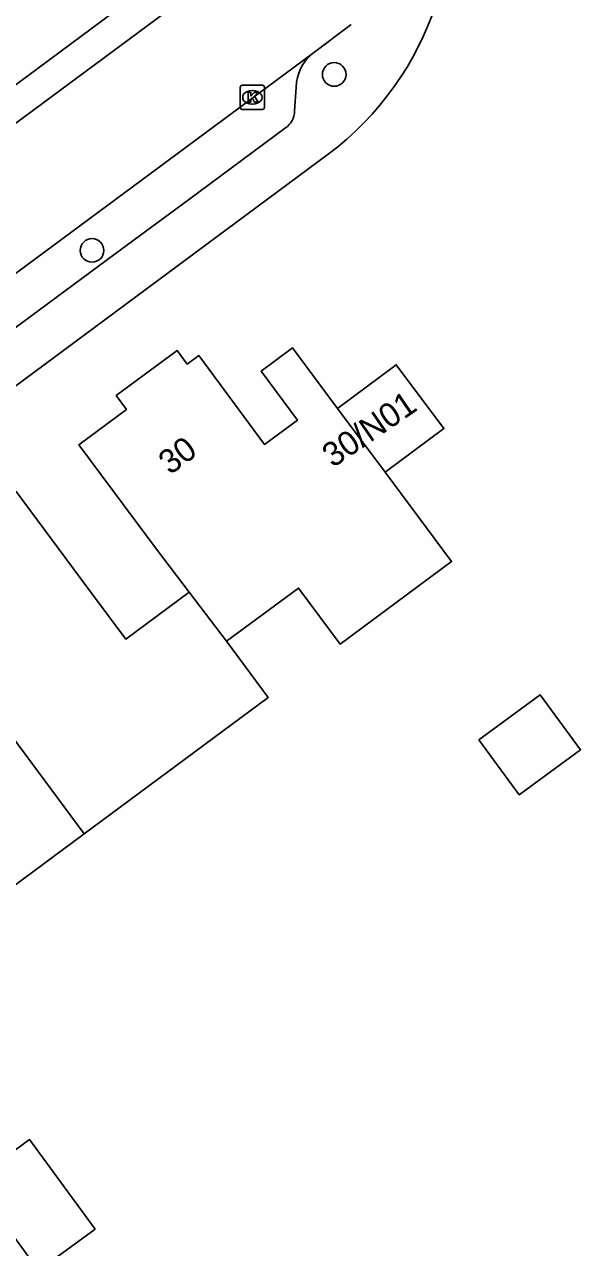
# Model space of a CAD drawing. Extents: x 163427 to 164190, y 380331 to 381641.
# Drawn here: x 163904.6 to 163927.7, y 381101.7 to 381152.4 of the extents above; entities that cross this region are included whole.
import ezdxf

# ---------------------------------------------------------------- set-up
doc = ezdxf.new("R2010")
doc.units = 0
for name, color, linetype in [('IMGEO_Boom', 7, 'Continuous'), ('IMGEO_Kolk', 7, 'Continuous'), ('IMGEO_Pand', 7, 'Continuous'), ('IMGEO_Pand_nummerreeks', 7, 'Continuous'), ('IMGEO_Rijbaan_lokaal_open', 7, 'Continuous'), ('IMGEO_Voetpad_open', 7, 'Continuous')]:
    doc.layers.add(name, color=color, linetype=linetype)

msp = doc.modelspace()

# ---------------------------------------------------------------- linework, layer by layer
at = {"layer": 'IMGEO_Boom'}
for centre in [(163917.466, 381150.293), (163907.429, 381142.998)]:
    msp.add_circle(centre, 0.489, dxfattribs=at)
at = {"layer": 'IMGEO_Kolk'}
for p, q in [((163913.572, 381148.918), (163913.572, 381149.77)), ((163913.647, 381149.844), (163914.499, 381149.844)), ((163914.573, 381149.77), (163914.573, 381148.918)), ((163914.06, 381149.624), (163914.085, 381149.624)), ((163914.499, 381148.844), (163913.647, 381148.844)), ((163914.083, 381149.064), (163914.058, 381149.064))]:
    msp.add_line(p, q, dxfattribs=at)
for points in [[(163913.572, 381148.918), (163913.572, 381149.77)], [(163913.647, 381149.844), (163914.499, 381149.844)], [(163914.573, 381149.77), (163914.573, 381148.918)], [(163913.893, 381149.544), (163914.016, 381149.544), (163914.016, 381149.393), (163914.146, 381149.544), (163914.31, 381149.544), (163914.164, 381149.393), (163914.317, 381149.144), (163914.165, 381149.144), (163914.08, 381149.308), (163914.016, 381149.241), (163914.016, 381149.144), (163913.893, 381149.144), (163913.893, 381149.544)], [(163914.499, 381148.844), (163913.647, 381148.844)]]:
    msp.add_lwpolyline(points, dxfattribs=at)
for centre, start, end in [((163913.649, 381149.768), 91.552, 178.448), ((163913.649, 381149.768), 91.552, 178.448), ((163914.497, 381149.768), 1.552, 88.448), ((163914.497, 381149.768), 1.552, 88.448), ((163913.649, 381148.92), 181.552, 268.448), ((163913.649, 381148.92), 181.552, 268.448), ((163914.497, 381148.92), 271.552, 358.448), ((163914.497, 381148.92), 271.552, 358.448)]:
    msp.add_arc(centre, 0.0765, start, end, dxfattribs=at)
for centre, major_axis, ratio, start_param, end_param in [((163914.059, 381149.344), (-0.387, 0.002), 0.722429, 4.712389, 7.853982), ((163914.084, 381149.344), (-0.39, 0.002), 0.717154, 1.570796, 4.712389)]:
    msp.add_ellipse(centre, major_axis=major_axis, ratio=ratio, start_param=start_param, end_param=end_param, dxfattribs=at)
at = {"layer": 'IMGEO_Pand'}
for points in [[(163911.457, 381128.826), (163910.136, 381130.556), (163906.878, 381134.938), (163908.856, 381136.409), (163908.433, 381136.98), (163910.953, 381138.853), (163911.376, 381138.283), (163911.857, 381138.641), (163914.574, 381134.957), (163915.944, 381135.968), (163914.442, 381137.988), (163915.742, 381138.955), (163917.249, 381136.93), (163917.607, 381136.448)], [(163919.576, 381133.801), (163922.01, 381135.611), (163920.04, 381138.258), (163917.607, 381136.448)], [(163917.607, 381136.448), (163919.576, 381133.801)], [(163919.576, 381133.801), (163922.33, 381130.099), (163917.712, 381126.679), (163915.991, 381129.004), (163913.008, 381126.795)], [(163911.457, 381128.826), (163908.835, 381126.878), (163907.537, 381128.624), (163904.279, 381133.006), (163903.797, 381132.65), (163903.374, 381133.22), (163900.854, 381131.347), (163901.27, 381130.787), (163899.295, 381129.331), (163903.828, 381123.229)], [(163913.008, 381126.795), (163911.457, 381128.826)], [(163907.102, 381118.82), (163914.73, 381124.47), (163913.008, 381126.795)], [(163923.466, 381122.709), (163925.138, 381120.435), (163927.676, 381122.3), (163926.003, 381124.574), (163923.466, 381122.709)], [(163903.828, 381123.229), (163907.102, 381118.82)], [(163897.841, 381115.561), (163900.823, 381117.77), (163902.545, 381115.445), (163907.102, 381118.82)], [(163907.553, 381102.419), (163905.209, 381100.711), (163902.5, 381104.428), (163904.843, 381106.137), (163907.553, 381102.419)]]:
    msp.add_lwpolyline(points, dxfattribs=at)
at = {"layer": 'IMGEO_Rijbaan_lokaal_open'}
for points in [[(163878.809, 381129.42), (163911.186, 381153.408)], [(163918.164, 381152.365), (163916.554, 381151.141)], [(163880.923, 381124.832), (163884.68, 381127.548), (163916.554, 381151.141)]]:
    msp.add_lwpolyline(points, dxfattribs=at)
at = {"layer": 'IMGEO_Voetpad_open'}
for points in [[(163911.894, 381155.545), (163877.893, 381130.301)], [(163915.886, 381149.771), (163915.823, 381148.771)], [(163915.45, 381148.075), (163911.422, 381145.095), (163908.391, 381142.852), (163903.871, 381139.507), (163900.842, 381137.267), (163896.214, 381133.842), (163893.166, 381131.587), (163888.806, 381128.36), (163885.739, 381126.089), (163884.183, 381124.937)], [(163882.189, 381120.998), (163883.08, 381121.66), (163884.455, 381122.693), (163917.22, 381146.987)]]:
    msp.add_lwpolyline(points, dxfattribs=at)
for centre, radius, start, end in [((163909.481, 381157.262), 12.864, 306.9864, 16.2453), ((163917.732, 381149.719), 1.847, 129.6332, 178.3799), ((163914.954, 381148.789), 0.869, 304.7945, 358.83)]:
    msp.add_arc(centre, radius, start, end, dxfattribs=at)

# ---------------------------------------------------------------- texts
at = {"layer": 'IMGEO_Pand_nummerreeks'}
for s, rotation, p in [('30/N01', 34.4184, (163917.414, 381133.967)), ('30', 36.6407, (163910.664, 381133.667))]:
    msp.add_text(s, height=1, rotation=rotation, dxfattribs=at).set_placement(p)

doc.saveas('drawing.dxf')
